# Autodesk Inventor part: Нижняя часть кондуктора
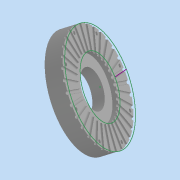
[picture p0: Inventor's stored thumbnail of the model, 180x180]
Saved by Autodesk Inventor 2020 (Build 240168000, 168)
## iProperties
Created: 2024-03
Part Number: Нижняя часть кондуктора
Material: Типовые
Document SubType Name: Modeling
Designer: User
Density: 1 g/cm^3
Appearance: Светло-серый
Author: User
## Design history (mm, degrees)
sketch "Эскиз1"
  geometry: C1 r 16 at (0, 0); C2 r 46 at (0, 0); 1 further point
  constraints: 2 centre point, 2 coincident
  dimensions: "d0" = 32 diameter of C1; "d1" = 92 diameter of C2
extrude "Выдавливание1" new body sketch "Эскиз1" distance "d2" = 2; taper "d3" = 0 deg
sketch "Эскиз2"
  geometry: C1 r 26 at (0, 0); C2 r 36 at (0, 0); C3 r 46 at (0, 0); 1 further point
  constraints: 3 centre point, 3 coincident
  dimensions: "d4" = 52 diameter of C1; "d14" = 92 diameter of C3
extrude "Выдавливание2" join sketch "Эскиз2" distance "d5" = 6.05; taper "d6" = 0 deg
sketch "Эскиз3"
  geometry: L1 (0, 46)-(0, 26); 3 further points
  constraints: 2 end point, 2 vertical alignment, 1 vertical, 2 other
node "РабПлоскость1"
sketch "Эскиз5"
  geometry: L1 (0, -46)-(0, 46) reference; L2 (0, 0)-(-1.5, 0); C1 r 1.5 at (-1.5, 0); 1 further point
  constraints: 2 end point, 1 centre point, 1 coincident, 1 horizontal, 1 midpoint
  dimensions: "d15" = 1.5 distance of L2.start L2.end; "d16" = 3 diameter of C1
extrude "Выдавливание4" cut sketch "Эскиз5" distance "d17" = 40; taper "d18" = 0 deg
sketch "Эскиз6"
  geometry: C1 r 16 at (0, 0); C2 r 46 at (0, 0); 1 further point
  constraints: 2 centre point, 2 coincident
extrude "Выдавливание5" join sketch "Эскиз6" distance "d22" = 8; taper "d23" = 0 deg
sketch "Эскиз7"
  geometry: L1 (-8.974, 45.116)-(-5.072, 25.5) reference; C1 r 1.5 at (-4.099, 41.618); A1 r 46 centre (0, 0) between (0, 46) and (-8.974, 45.116) reference; 1 further point
  constraints: 1 centre point
  dimensions: "d26" = 3 diameter of C1
extrude "Выдавливание6" cut sketch "Эскиз7" distance "d27" = 40; taper "d28" = 0 deg
sketch "Эскиз8"
  geometry: C1 r 26 at (0, 0); C2 r 46 at (0, 0); C3 r 1.5 at (-4.099, 41.618) reference; C4 r 1.5 at (-4.099, 41.618); 1 further point
  constraints: 3 centre point, 3 coincident
  dimensions: "d29" = 3 diameter of C4
extrude "Выдавливание7" join sketch "Эскиз8" distance "d30" = 8; taper "d31" = 0 deg
pattern_circular "Круговой массив3" dims angle "d33" = 360 deg
sketch "Эскиз9"
  geometry: C1 r 1.5 at (0, 0) reference; C2 r 1.5 at (0, 0); 1 further point
  constraints: 1 centre point, 1 coincident
  dimensions: "d35" = 3 diameter of C2
extrude "Выдавливание8" cut sketch "Эскиз9" distance "d36" = 20; taper "d37" = 0 deg
sketch "Эскиз10"
  geometry: C1 r 1.5 at (0, 0) reference; C2 r 1.5 at (0, 0); C3 r 1.5 at (-15.088, -28.228) reference; C4 r 1.5 at (-15.088, -28.228); C5 r 1.5 at (-45.718, -37.519) reference; C6 r 1.5 at (-45.718, -37.519); C7 r 1.5 at (-73.946, -22.431) reference; C8 r 1.5 at (-73.946, -22.431); C9 r 1.5 at (-83.237, 8.198) reference; C10 r 1.5 at (-83.237, 8.198); C11 r 1.5 at (-68.149, 36.426) reference; C12 r 1.5 at (-68.149, 36.426); 1 further point
  constraints: 6 centre point, 6 coincident
  dimensions: "d38" = 3 diameter of C2; "d39" = 3 diameter of C4; "d40" = 3 diameter of C6; "d41" = 3 diameter of C8; "d42" = 3 diameter of C10; "d43" = 3 diameter of C12
extrude "Выдавливание9" cut sketch "Эскиз10" distance "d44" = 20; taper "d45" = 0 deg
sketch "Эскиз11"
  geometry: L1 (-67.84, -80.836)-(62.77, -80.836); L2 (62.77, -80.836)-(62.77, 74.439); L3 (62.77, 74.439)-(-67.84, 74.439); L4 (-67.84, 74.439)-(-67.84, -80.836); 1 further point
  constraints: 8 end point, 2 parallel, 1 horizontal, 1 perpendicular
extrude "Выдавливание10" cut sketch "Эскиз11" distance "d46" = 9.5; taper "d47" = 0 deg
node "Твердое тело1"
pattern_circular "Круговой массив2" dims angle "d20" = 360 deg
